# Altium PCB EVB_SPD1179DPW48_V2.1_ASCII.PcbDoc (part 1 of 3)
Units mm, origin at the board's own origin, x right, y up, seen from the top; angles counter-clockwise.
Board outline 135 x 90 mm, 4 copper layers (Top Layer, GND, L3, Bottom Layer), stack 0.603 mm thick; 322 components, 156 nets, 727 pads, 939 vias.
Unrouted connection lines stored in the file: 172.
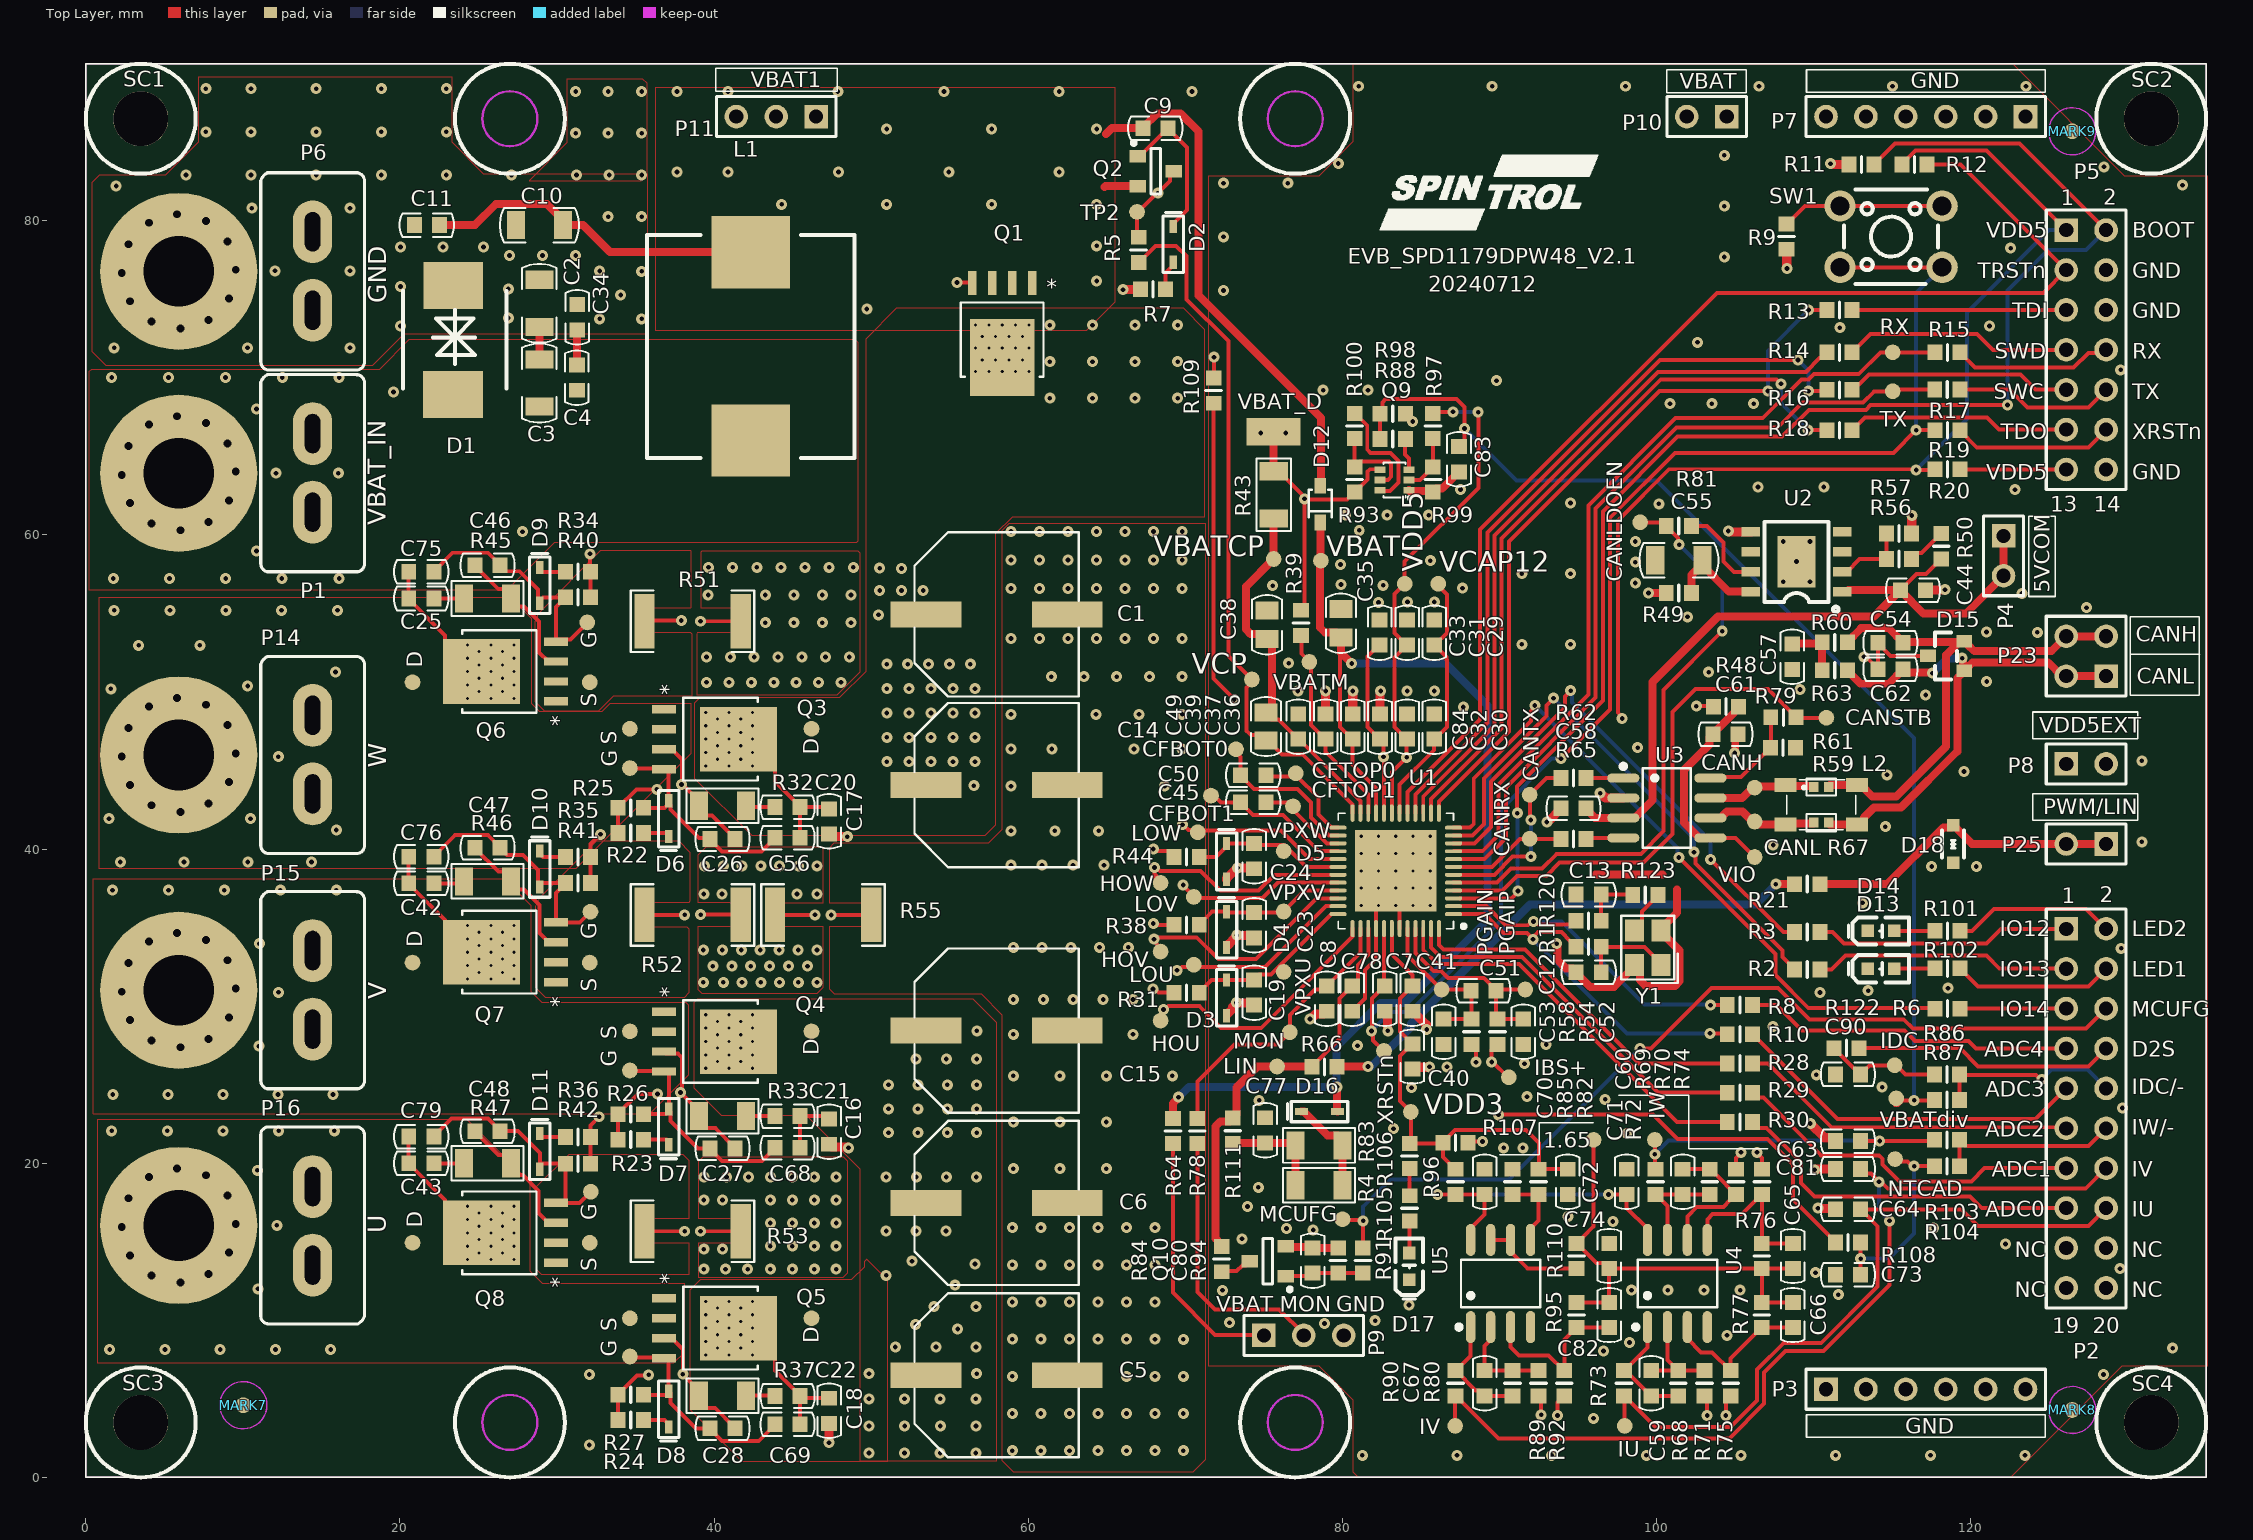
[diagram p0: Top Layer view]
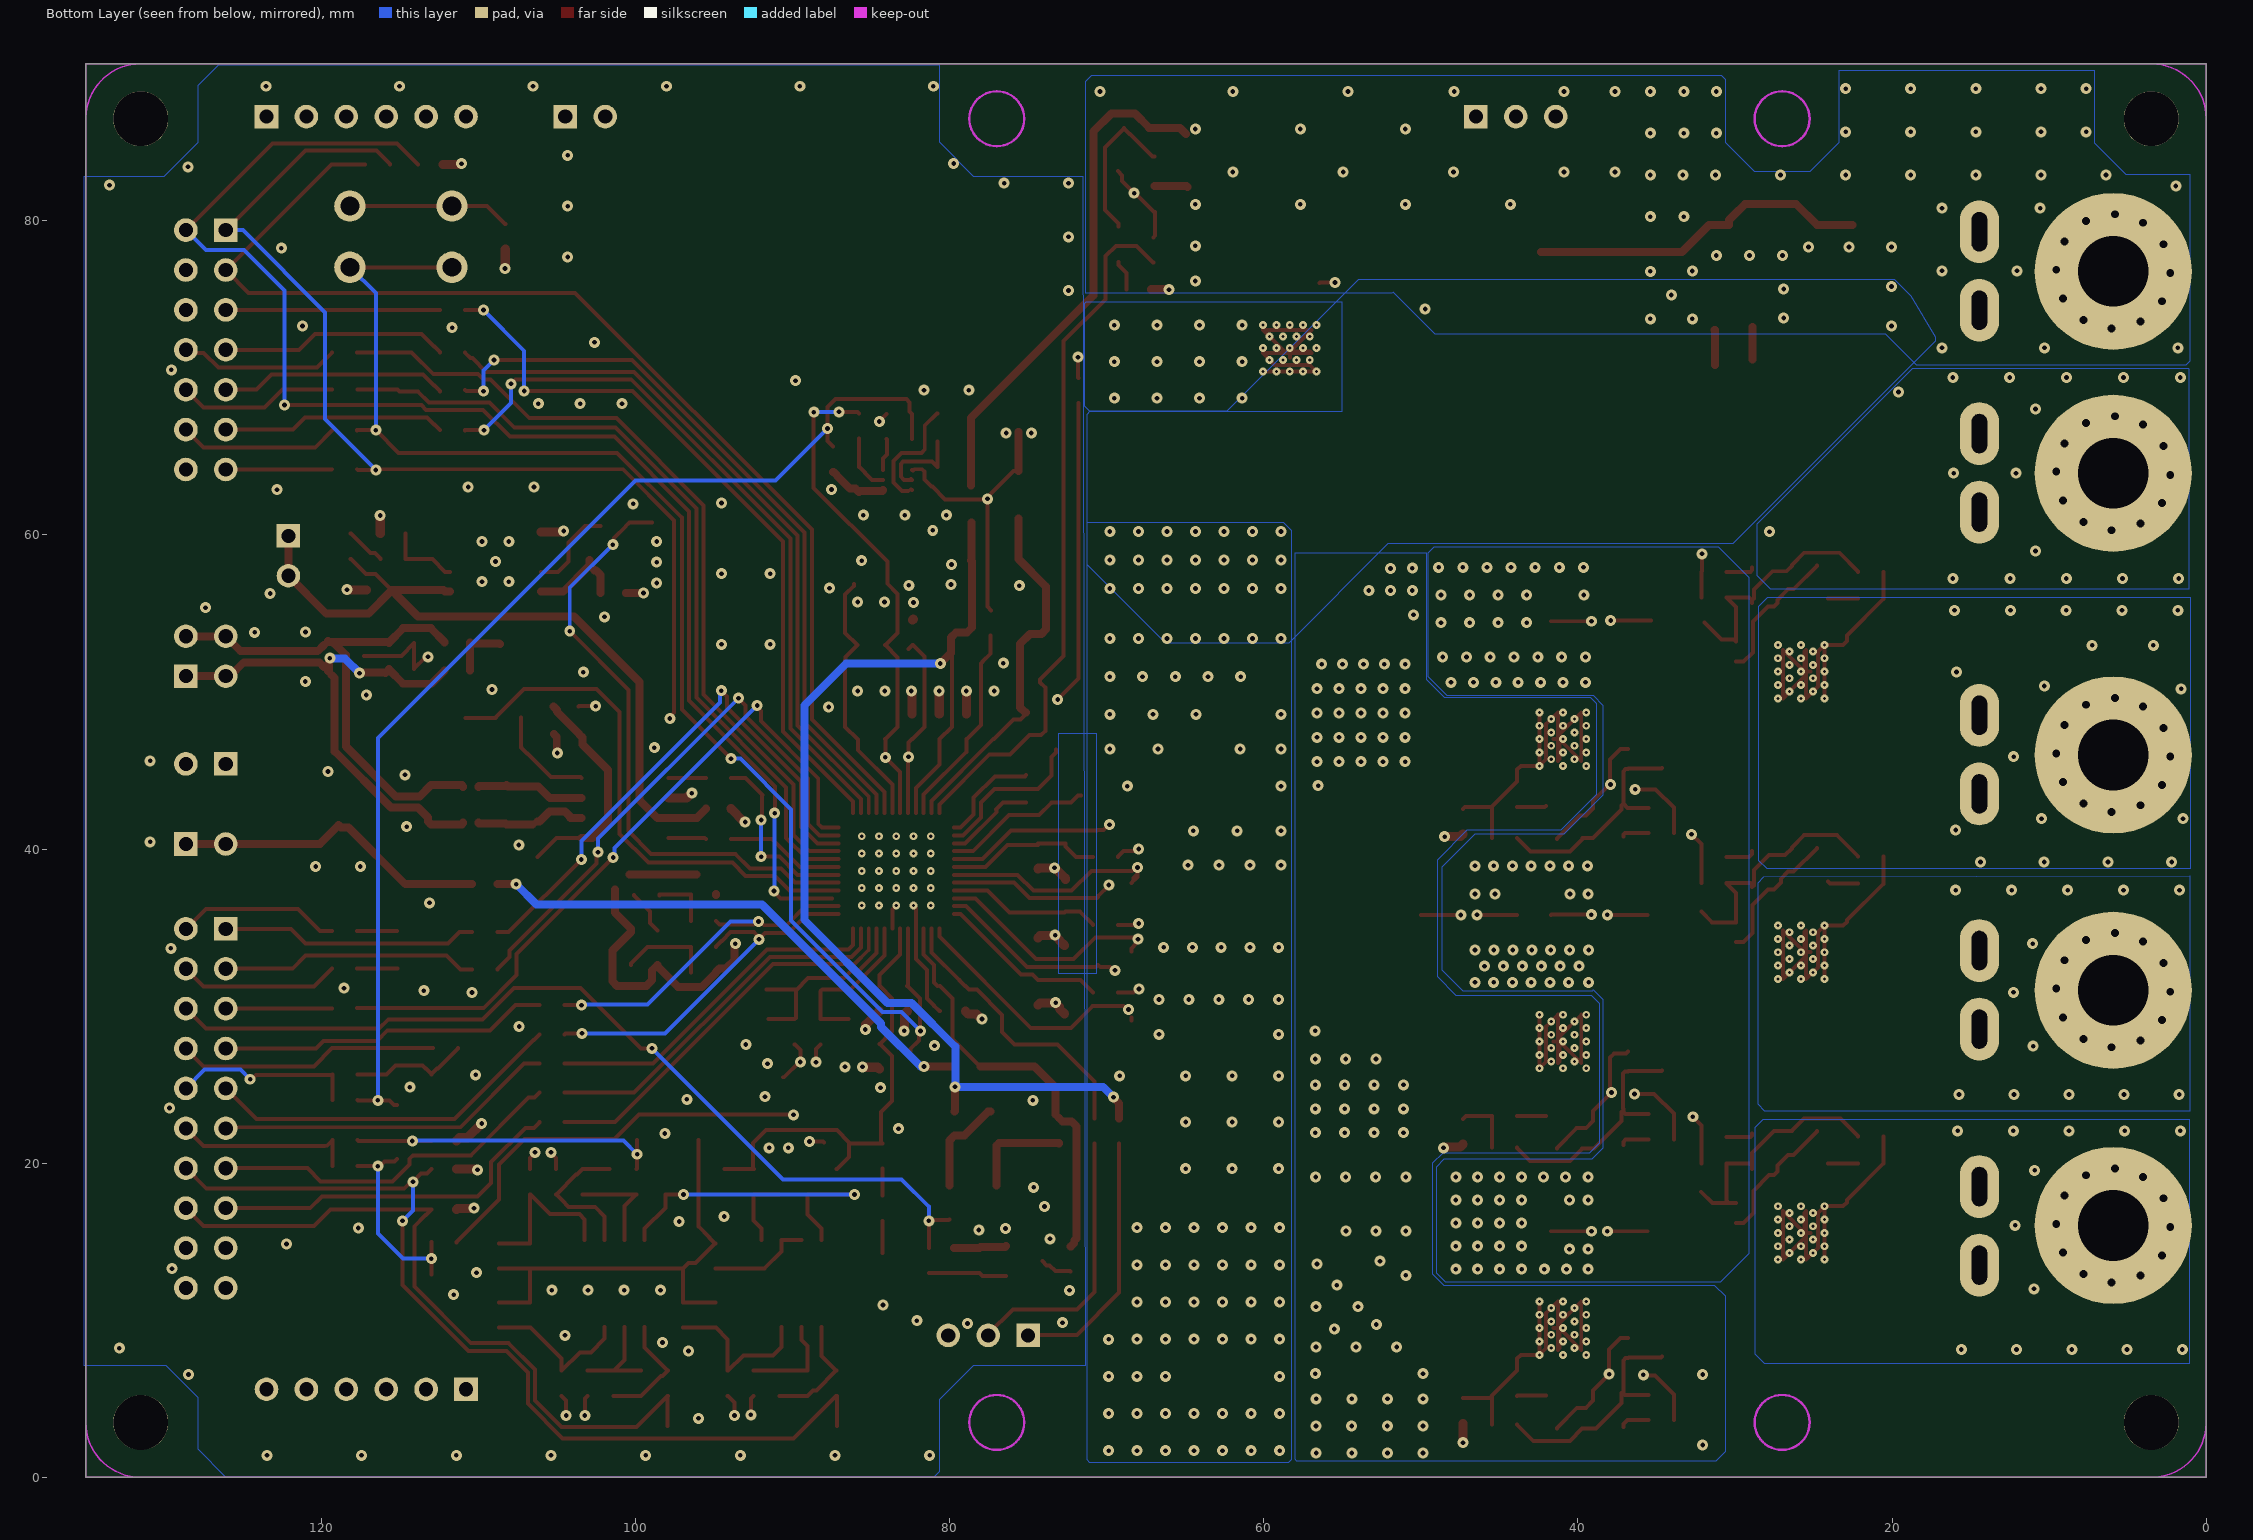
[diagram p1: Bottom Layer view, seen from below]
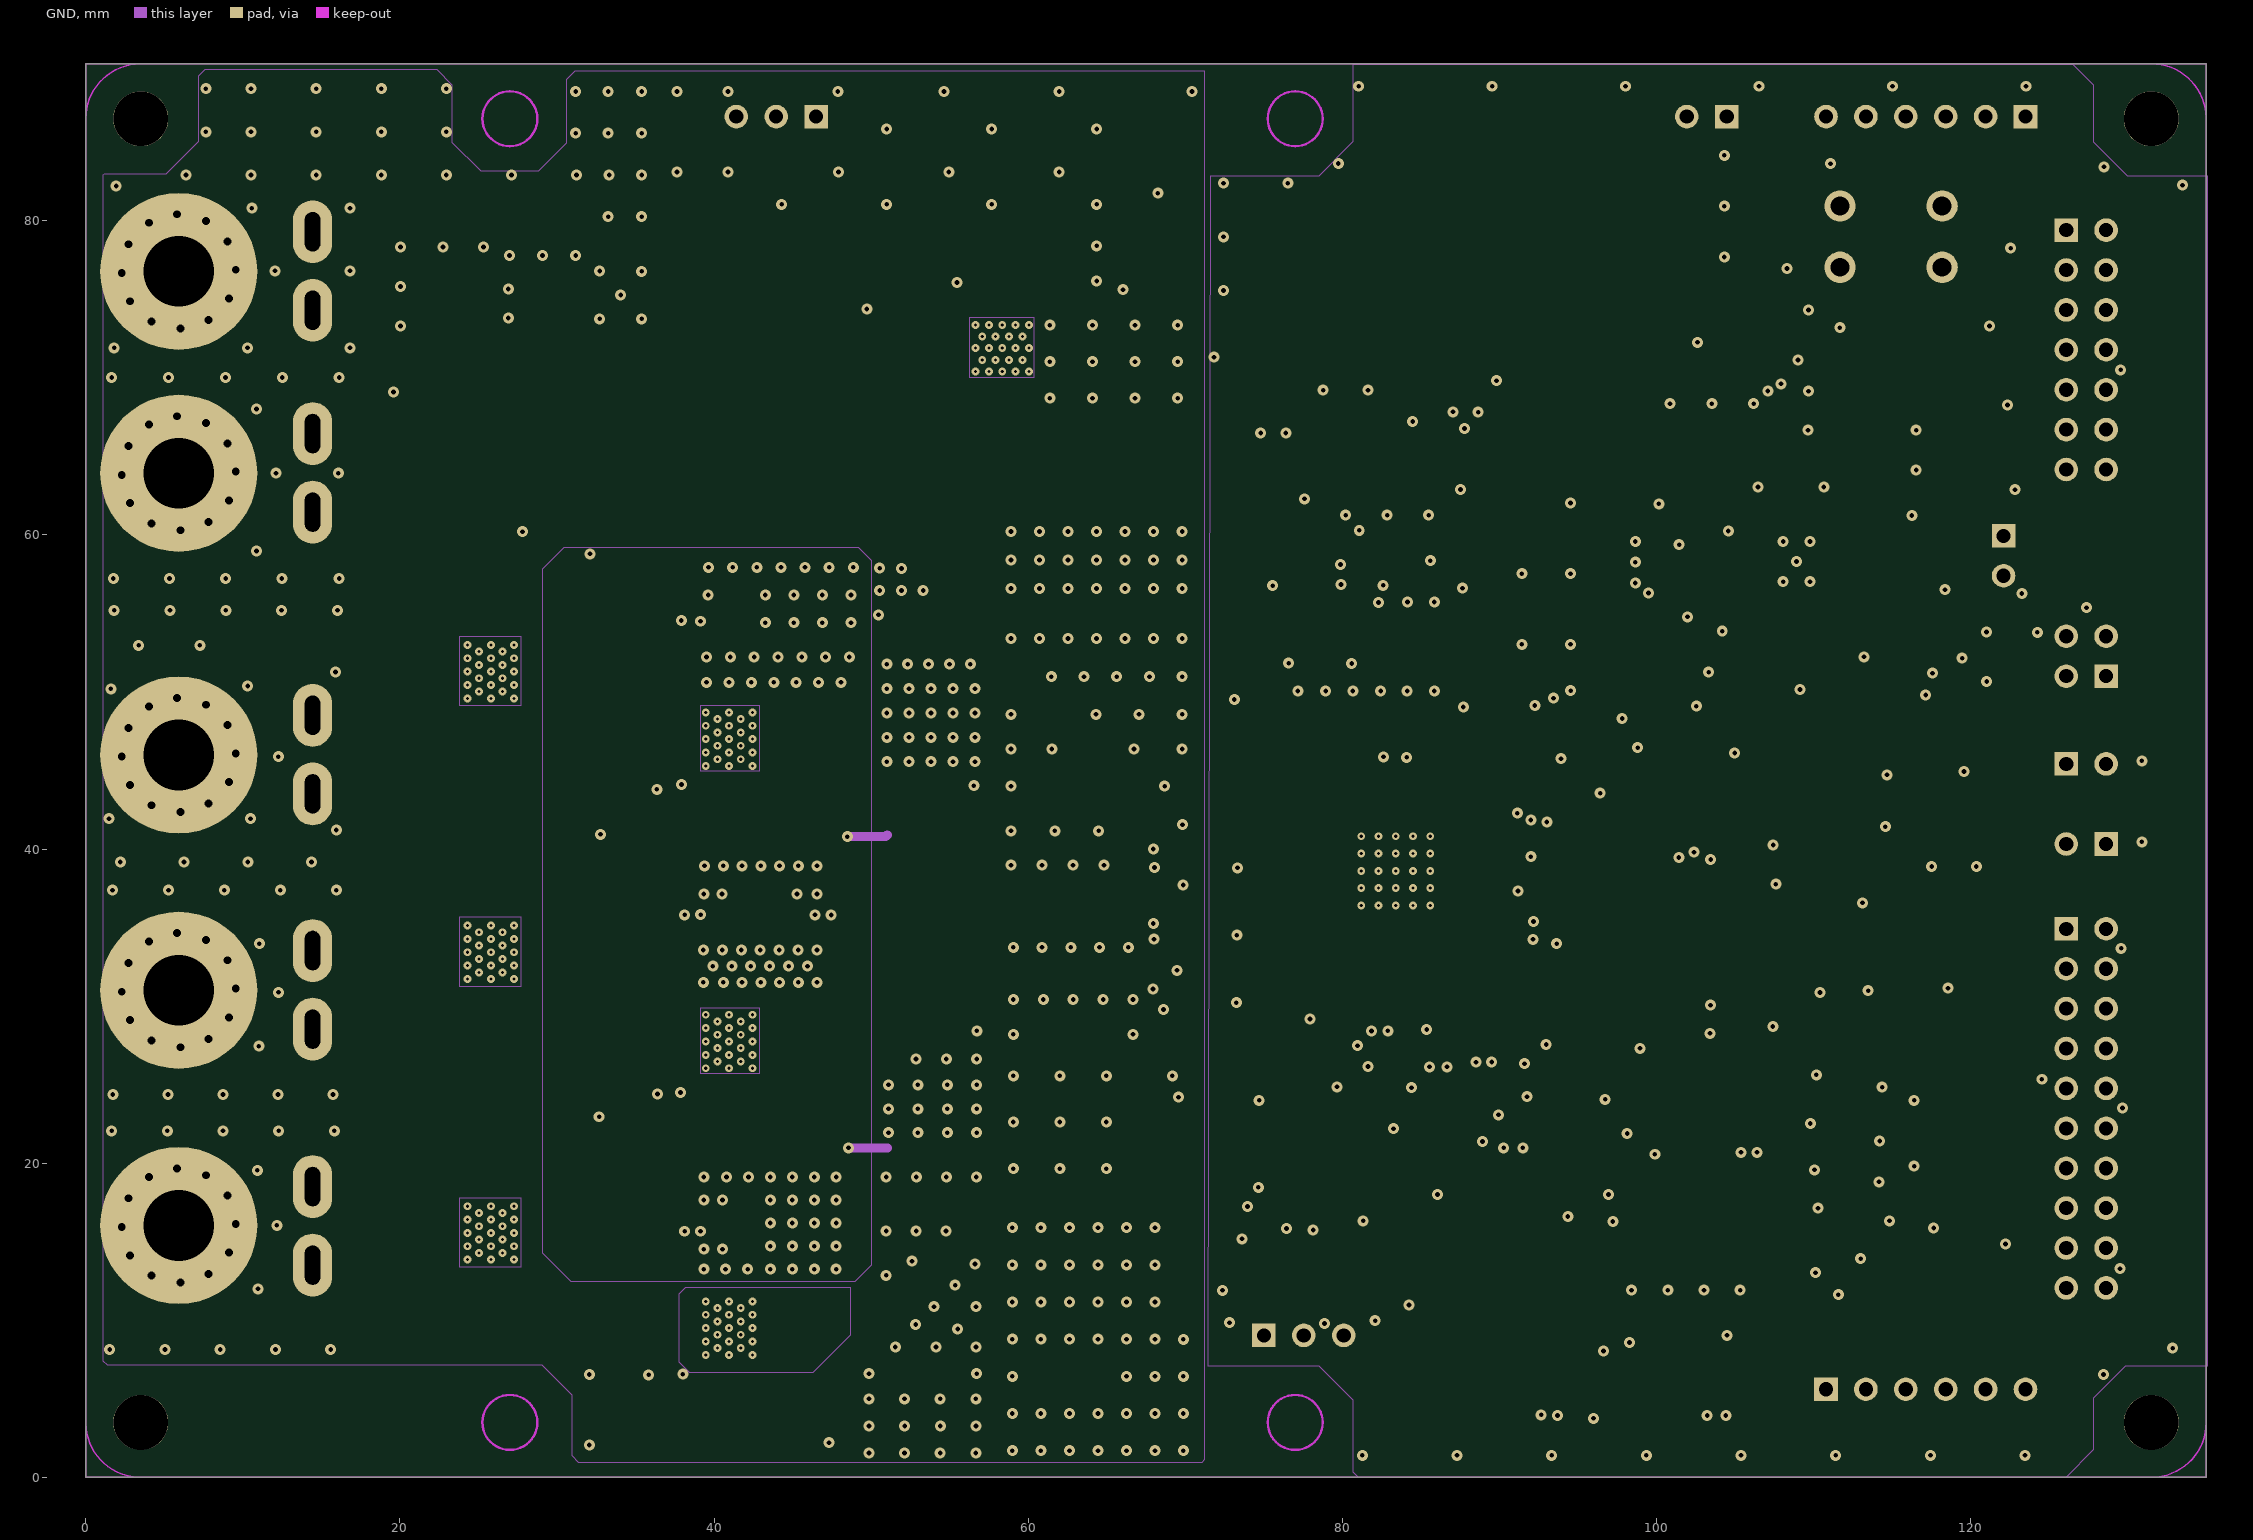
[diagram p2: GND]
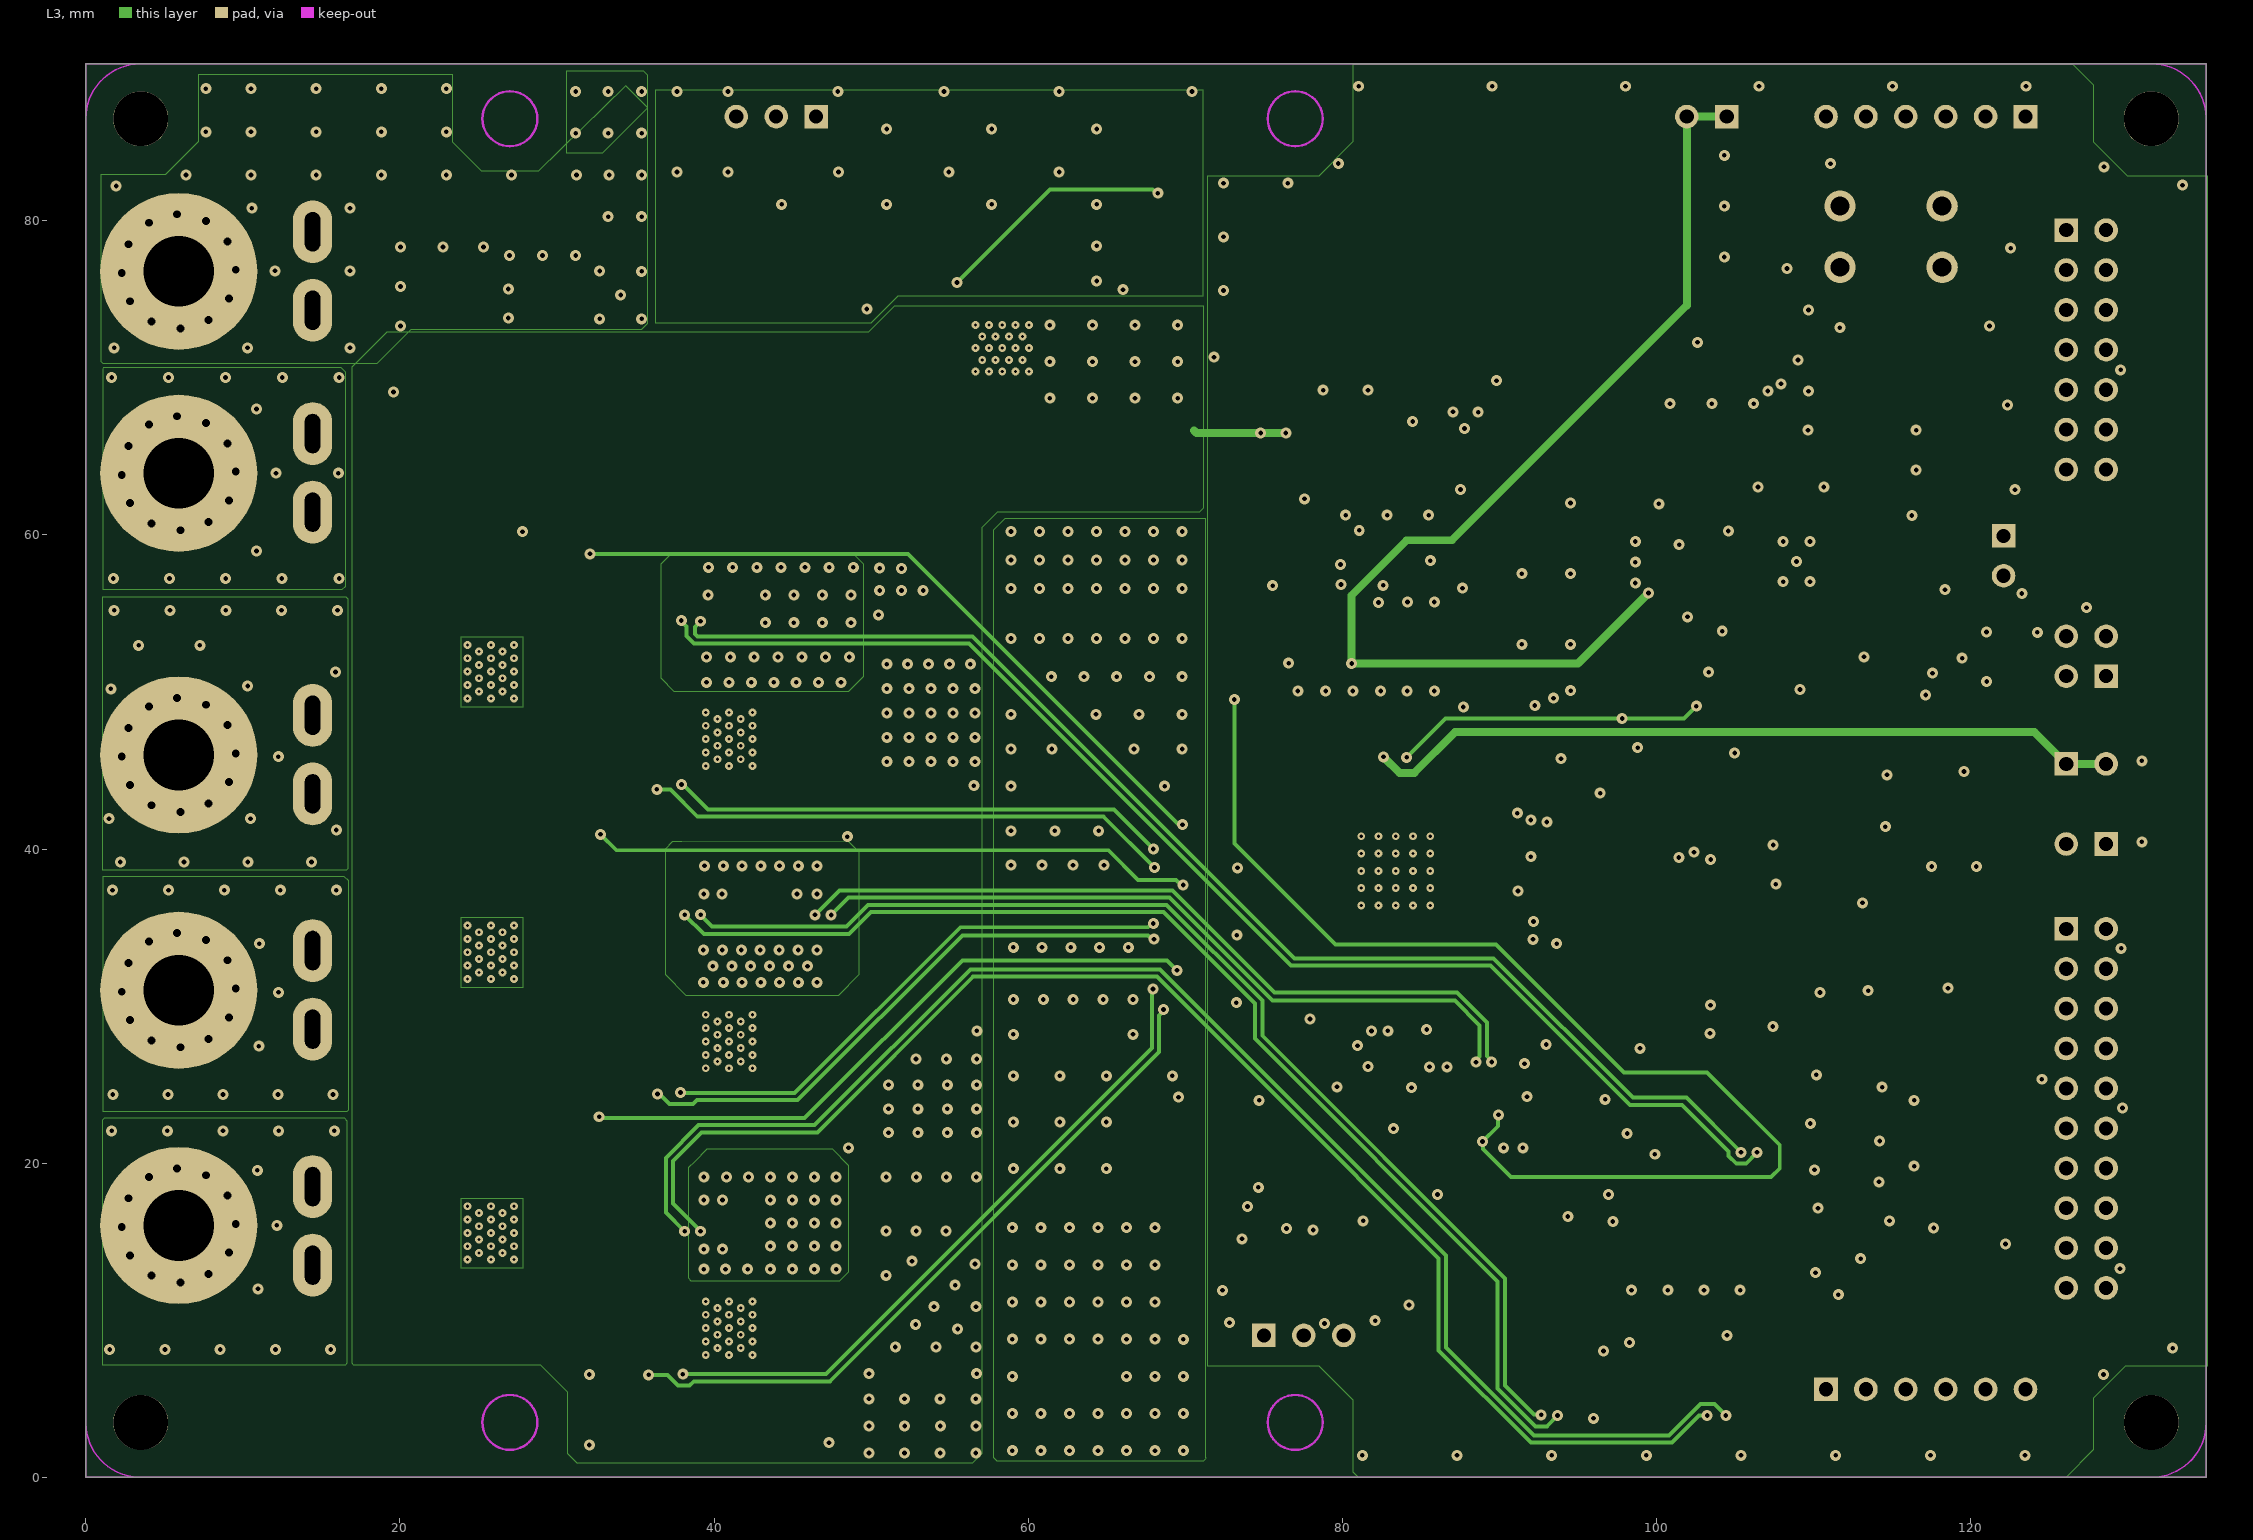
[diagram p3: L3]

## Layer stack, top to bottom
Top Solder: solder mask 0.0102, Solder Resist, Dk 3.5
Top Layer: signal copper 0.0356
Dielectric 2: prepreg 0.0711, PP-006, Dk 4.1
GND: signal copper 0.035
Dielectric 1: dielectric 0.32, FR-4, Dk 4.8
L3: signal copper 0.035
Dielectric 3: prepreg 0.0711, PP-006, Dk 4.1
Bottom Layer: signal copper 0.0356
Bottom Solder: solder mask 0.0102, Solder Resist, Dk 3.5

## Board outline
0,0 135,0 135,90 0,90

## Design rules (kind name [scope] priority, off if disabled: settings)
AssemblyTestPointUsage [All] p0: scope1count=1 scope1_0_kind=Board scope1_0_value=Board scope2count=1 scope2_0_kind=Board scope2_0_value=Board commentlength=0
AssemblyTestpoint [All] p0: scope1count=1 scope1_0_kind=Board scope1_0_value=Board scope2count=1 scope2_0_kind=Board scope2_0_value=Board commentlength=0
Clearance Clearance_LC [All] p0 off: scope1count=1 scope1_0_kind=Board scope1_0_value=Board scope2count=1 scope2_0_kind=Board scope2_0_value=Board commentlength=59 gap=0.3 // Protel DXP Scope 1 Expression Was: InNamedPolygon('LC')
Clearance Clearance_keepout [All] p0 off: scope1count=1 scope1_0_kind=Board scope1_0_value=Board scope2count=1 scope2_0_kind=Board scope2_0_value=Board commentlength=48 gap=1 // Protel DXP Scope 1 Expression Was: IsKeepOut
Clearance [All] p0: scope1count=1 scope1_0_kind=Board scope1_0_value=Board scope2count=1 scope2_0_kind=Board scope2_0_value=Board commentlength=0 gap=0.5
Clearance Clearance_LC [InNamedPolygon('LC')] p1: gap=0.3 ignorepadtopadclearanceinfootprint=FALSE except(0: Arc-Hole Track-Hole SMDPad-Hole THPad-Hole Via-Hole Fill-Hole Poly-Hole Region-Hole Text-Hole; 0.178: Arc-SMDPad Track-SMDPad SMDPad-SMDPad; 0.203: Arc-Arc Arc-Track Track-Track; 0.254: Arc-THPad Arc-Via Arc-Text Track-THPad Track-Via Track-Text SMDPad-THPad SMDPad-Via SMDPad-Text THPad-THPad THPad-Via THPad-Text Via-Via Via-Text Fill-Text Poly-Text Region-Text Text-Text)
Clearance Clearance_keepout [IsKeepOut] p2: gap=1 ignorepadtopadclearanceinfootprint=FALSE except(0: Arc-Hole Track-Hole SMDPad-Hole THPad-Hole Via-Hole Fill-Hole Poly-Hole Region-Hole Text-Hole; 0.178: Arc-SMDPad Track-SMDPad SMDPad-SMDPad; 0.203: Arc-Arc Arc-Track Track-Track; 0.254: Arc-THPad Arc-Via Arc-Text Track-THPad Track-Via Track-Text SMDPad-THPad SMDPad-Via SMDPad-Text THPad-THPad THPad-Via THPad-Text Via-Via Via-Text Fill-Text Poly-Text Region-Text Text-Text)
Clearance [All] p3: gap=0.5 ignorepadtopadclearanceinfootprint=FALSE except(0: Arc-Hole Track-Hole SMDPad-Hole THPad-Hole Via-Hole Fill-Hole Poly-Hole Region-Hole Text-Hole; 0.178: Arc-SMDPad Track-SMDPad SMDPad-SMDPad; 0.203: Arc-Arc Arc-Track Track-Track; 0.254: Arc-THPad Arc-Via Arc-Text Track-THPad Track-Via Track-Text SMDPad-THPad SMDPad-Via SMDPad-Text THPad-THPad THPad-Via THPad-Text Via-Via Via-Text Fill-Text Poly-Text Region-Text Text-Text)
ComponentClearance [All] p0: scope1count=1 scope1_0_kind=Board scope1_0_value=Board scope2count=1 scope2_0_kind=Board scope2_0_value=Board commentlength=0 gap=0.05 collisioncheckmode=3
ComponentClearance [All] p1: gap=0.05 collisioncheckmode=3 verticalgap=0.05 showdistances=FALSE
DiffPairsRouting [All] p0: scope1count=1 scope1_0_kind=Board scope1_0_value=Board scope2count=1 scope2_0_kind=Board scope2_0_value=Board commentlength=0
FabricationTestPointUsage [All] p0: scope1count=1 scope1_0_kind=Board scope1_0_value=Board scope2count=1 scope2_0_kind=Board scope2_0_value=Board commentlength=0 valid=0 allowmultiple=FALSE
FabricationTestpoint [All] p0: scope1count=1 scope1_0_kind=Board scope1_0_value=Board scope2count=1 scope2_0_kind=Board scope2_0_value=Board commentlength=0 side=3 testpointundercomponent=TRUE minsize=1.016 maxsize=2.54 preferedsize=1.524 minholesize=0 maxholesize=1.016 preferedholesize=0.813 testpointgrid=0.025
FanoutControl Fanout_BGA [All] p0 off: scope1count=1 scope1_0_kind=Board scope1_0_value=Board scope2count=1 scope2_0_kind=Board scope2_0_value=Board commentlength=69 // Protel DXP Scope 1 Expression Was: IsBGA   Fanout_BGA (Default Rule)
FanoutControl Fanout_LCC [All] p0 off: scope1count=1 scope1_0_kind=Board scope1_0_value=Board scope2count=1 scope2_0_kind=Board scope2_0_value=Board commentlength=69 // Protel DXP Scope 1 Expression Was: IsLCC   Fanout_LCC (Default Rule)
FanoutControl Fanout_SOIC [All] p0 off: scope1count=1 scope1_0_kind=Board scope1_0_value=Board scope2count=1 scope2_0_kind=Board scope2_0_value=Board commentlength=71 // Protel DXP Scope 1 Expression Was: IsSOIC   Fanout_SOIC (Default Rule)
FanoutControl Fanout_Small [All] p0 off: scope1count=1 scope1_0_kind=Board scope1_0_value=Board scope2count=1 scope2_0_kind=Board scope2_0_value=Board commentlength=84 // Protel DXP Scope 1 Expression Was: (CompPinCount < 5)   Fanout_Small (Default Rule)
FanoutControl Fanout_Default [All] p0: scope1count=1 scope1_0_kind=Board scope1_0_value=Board scope2count=1 scope2_0_kind=Board scope2_0_value=Board commentlength=30 // Fanout_Default (Default Rule)
Height [All] p0: scope1count=1 scope1_0_kind=Board scope1_0_value=Board scope2count=1 scope2_0_kind=Board scope2_0_value=Board commentlength=0
HoleSize [All] p0: scope1count=1 scope1_0_kind=Board scope1_0_value=Board scope2count=1 scope2_0_kind=Board scope2_0_value=Board commentlength=0 absolutevalues=TRUE maxlimit=10 minlimit=0.025 maxpercent=80.000 minpercent=20.000
HoleSize [All] p1: absolutevalues=TRUE maxlimit=10 minlimit=0.025 maxpercent=80.000 minpercent=20.000
HoleToHoleClearance [All] p0: scope1count=1 scope1_0_kind=Board scope1_0_value=Board scope2count=1 scope2_0_kind=Board scope2_0_value=Board commentlength=0
HoleToHoleClearance [All] p1: gap=0.1 allowstackedmicrovias=TRUE
LayerPairs [All] p0: scope1count=1 scope1_0_kind=Board scope1_0_value=Board scope2count=1 scope2_0_kind=Board scope2_0_value=Board commentlength=0 enforce=TRUE
MinimumSolderMaskSliver [All] p0: scope1count=1 scope1_0_kind=Board scope1_0_value=Board scope2count=1 scope2_0_kind=Board scope2_0_value=Board commentlength=0
MinimumSolderMaskSliver [All] p1: minsoldermaskwidth=0.02
NetAntennae [All] p0: scope1count=1 scope1_0_kind=Board scope1_0_value=Board scope2count=1 scope2_0_kind=Board scope2_0_value=Board commentlength=0
PasteMaskExpansion [All] p0: scope1count=1 scope1_0_kind=Board scope1_0_value=Board scope2count=1 scope2_0_kind=Board scope2_0_value=Board commentlength=0 expansion=0
PlaneClearance [All] p0: scope1count=1 scope1_0_kind=Board scope1_0_value=Board scope2count=1 scope2_0_kind=Board scope2_0_value=Board commentlength=0 clearance=0.508
PlaneConnect [All] p0: scope1count=1 scope1_0_kind=Board scope1_0_value=Board scope2count=1 scope2_0_kind=Board scope2_0_value=Board commentlength=0 planeconnectstyle=Relief reliefexpansion=0.508 reliefentries=4 reliefconductorwidth=0.254 reliefairgap=0.254
PolygonConnect PolygonConnect_1 [All] p0: scope1count=1 scope1_0_kind=Footprint scope1_0_value=TP-1.0 scope2count=1 scope2_0_kind=Board scope2_0_value=Board commentlength=0 connectstyle=Direct reliefconductorwidth=0.254 reliefentries=4 polygonreliefangle="90 Angle"
PolygonConnect PolygonConnect_direct [All] p0: scope1count=1 scope1_0_kind=ComponentClass scope1_0_value=direct scope2count=1 scope2_0_kind=Board scope2_0_value=Board commentlength=0 connectstyle=Direct reliefconductorwidth=0.254 reliefentries=4 polygonreliefangle="90 Angle"
PolygonConnect [All] p0: scope1count=1 scope1_0_kind=Board scope1_0_value=Board scope2count=1 scope2_0_kind=Board scope2_0_value=Board commentlength=0 connectstyle=Direct reliefconductorwidth=0.254 reliefentries=4 polygonreliefangle="90 Angle"
PolygonConnect PolygonConnect_1 [HasFootprint('TP-1.0')] p1: connectstyle=Direct reliefconductorwidth=0.254 reliefentries=4 polygonreliefangle="90 Angle" airgapwidth=0.254
PolygonConnect PolygonConnect_direct [InComponentClass('direct')] p2: connectstyle=Direct reliefconductorwidth=0.254 reliefentries=4 polygonreliefangle="90 Angle" airgapwidth=0.254
PolygonConnect [All] p3: thpad.connectstyle=Direct thpad.reliefconductorwidth=0.254 thpad.reliefentries=4 thpad.polygonreliefangle="90 Angle" thpad.airgapwidth=0.254 smdpad.connectstyle=Relief smdpad.reliefconductorwidth=0.254 smdpad.reliefentries=4 smdpad.polygonreliefangle="90 Angle" smdpad.airgapwidth=0.254 via.connectstyle=Direct via.reliefconductorwidth=0.254 via.reliefentries=4 via.polygonreliefangle="90 Angle" via.airgapwidth=0.254
RoutingCorners [All] p0: scope1count=1 scope1_0_kind=Board scope1_0_value=Board scope2count=1 scope2_0_kind=Board scope2_0_value=Board commentlength=0 cornerstyle=45-Degree minsetback=2.54 maxsetback=2.54
RoutingLayers [All] p0: scope1count=1 scope1_0_kind=Board scope1_0_value=Board scope2count=1 scope2_0_kind=Board scope2_0_value=Board commentlength=0 top layer=Automatic mid layer 1=Automatic mid layer 2=Automatic bottom layer=Automatic
RoutingPriority [All] p0: scope1count=1 scope1_0_kind=Board scope1_0_value=Board scope2count=1 scope2_0_kind=Board scope2_0_value=Board commentlength=0
RoutingTopology [All] p0: scope1count=1 scope1_0_kind=Board scope1_0_value=Board scope2count=1 scope2_0_kind=Board scope2_0_value=Board commentlength=0 topology=Shortest
RoutingVias [All] p0: scope1count=1 scope1_0_kind=Board scope1_0_value=Board scope2count=1 scope2_0_kind=Board scope2_0_value=Board commentlength=0 holewidth=0.711 width=1.27 viastyle="Through Hole" minholewidth=0.711 minwidth=1.27 maxholewidth=0.711 maxwidth=1.27
RoutingVias [All] p1: holewidth=0.711 width=1.27 viastyle="Through Hole" minholewidth=0.711 minwidth=1.27 maxholewidth=0.711 maxwidth=1.27
ShortCircuit [All] p0: scope1count=1 scope1_0_kind=Board scope1_0_value=Board scope2count=1 scope2_0_kind=Board scope2_0_value=Board commentlength=0 allowed=FALSE
SilkToBoardRegionClearance [All] p0: scope1count=1 scope1_0_kind=Board scope1_0_value=Board scope2count=1 scope2_0_kind=Board scope2_0_value=Board commentlength=0
SilkToSilkClearance [All] p0: scope1count=1 scope1_0_kind=Board scope1_0_value=Board scope2count=1 scope2_0_kind=Board scope2_0_value=Board commentlength=0
SilkToSilkClearance [All] p1: silktosilkclearance=0.01
SilkToSolderMaskClearance [All] p0 off: scope1count=1 scope1_0_kind=Board scope1_0_value=Board scope2count=1 scope2_0_kind=Board scope2_0_value=Board commentlength=44 // Protel DXP Scope 1 Expression Was: IsPad
SilkToSolderMaskClearance [IsPad] p1: minsilkscreentomaskgap=0.01 clearancetoexposedcopper=TRUE
SolderMaskExpansion [All] p0: scope1count=1 scope1_0_kind=Board scope1_0_value=Board scope2count=1 scope2_0_kind=Board scope2_0_value=Board commentlength=0 expansion=0.102
SolderMaskExpansion [All] p1: expansion=0.102 istentingtop=FALSE
UnRoutedNet [All] p0: scope1count=1 scope1_0_kind=Board scope1_0_value=Board scope2count=1 scope2_0_kind=Board scope2_0_value=Board commentlength=0
UnpouredPolygon [All] p0: scope1count=1 scope1_0_kind=Board scope1_0_value=Board scope2count=1 scope2_0_kind=Board scope2_0_value=Board commentlength=0
Width [All] p0: scope1count=1 scope1_0_kind=Board scope1_0_value=Board scope2count=1 scope2_0_kind=Board scope2_0_value=Board commentlength=0 maxlimit=2.54 minlimit=0.203 preferedwidth=0.254
Width [All] p1: maxlimit=2.54 minlimit=0.203 preferedwidth=0.254
24 further rules are at their usual default settings.

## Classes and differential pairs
component class SPD1179_Demo_Board: 1.65 C1 C2 C3 C4 C5 C6 C7 C8 C9 C10 C11 C12 C13 C14 C15 C16 C17 C18 C19 C20 C21 C22 C23 C24 C25 C26 C27 C28 C29 C30 C31 C32 C33 C34 C35 C36 C37 C38 C39 C40 C41 C42 C43 C44 C45 C46 C47 C48 C49 C50 C51 C52 C53 C54 C55 C56 C57 C58 C59 C60 C61 C62 C63 C64 C65 C66 C67 C68 C69 C70 C71 C72 C73 C74 C75 C76 C77 C78 C79 C80 C81 C82 C83 C84 C90 CANH CANL CANLDOEN CANRX CANSTB CANTX CFBOT0 CFBOT1 CFTOP0 CFTOP1 D D1 D2 D3 D4 D5 D6 D7 D8 D9 D10 D11 D12 D13 D14 D15 D16 D17 D18 G HOU HOV HOW IBS+ IDC IU IV IW L1 L2 LIN LOU LOV LOW MCUFG MON NTCAD P1 P2 P3 P4 P5 P6 P7 P8 P9 P10 P14 P15 P16 P23 P25 PGAIN PGAIP Q1 Q2 Q3 Q4 Q5 Q6 Q7 Q8 Q9 Q10 R1 R2 R3 R4 R5 R6 R7 R8 R9 R10 R11 R12 R13 R14 R15 R16 R17 R18 R19 R20 R21 R22 R23 R24 R25 R26 R27 R28 R29 R30 R31 R32 R33 R34 R35 R36 R37 R38 R39 R40 R41 R42 R43 R44 R45 R46 R47 R48 R49 R50 R51 R52 R53 R54 R55 R56 R57 R58 R59 R60 R61 R62 R63 R64 R65 R66 R67 R68 R69 R70 R71 R72 R73 R74 R75 R76 R77 R78 R79 R80 R81 R82 R83 R84 R85 R86 R87 R88 R89 R90 R91 R92 R93 R94 R95 R96 R97 R98 R99 R100 R101 R102 R103 R104 R105 R106 R107 R108 R109 R110 R111 R120 R122 R123 RX S SW1 TP2 TX U1 U2 U3 U4 U5 VBAT VBAT_D VBATCP VBATDDIV VBATM VCAP12 VCP VDD3 VDD5 VIO VPXU VPXV VPXW Y1

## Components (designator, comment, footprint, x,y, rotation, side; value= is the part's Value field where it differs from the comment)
1.65 "TEST-Point" TP-1.0 95.996,21.488 r180 top (schematic designator TP35)
C1 "EEHZK1E471P" CAP-SMD_BD10.0-L10.3-W10.3-FD 57.988,54.947 r0 top
C2 "CAP" C1206 28.88,74.752 r270 top
C3 "CAP" C1206 28.88,69.672 r270 top
C4 "CAP" C0603 31.267,70.015 r270 top
C5 "EEHZK1E471P" CAP-SMD_BD10.0-L10.3-W10.3-FD 57.988,6.502 r0 top
C6 "EEHZK1E471P" CAP-SMD_BD10.0-L10.3-W10.3-FD 57.988,17.475 r0 top
C7 "CAP" C0603 82.703,30.48 r90 top
C8 "CAP" C0603 79.003,30.48 r90 top
C9 "CAP" C0603 68.097,85.903 r180 top
C10 "CAP" C1206 28.88,79.731 r180 top
C11 "CAP" C0603 21.717,79.731 r0 top
C12 "CAP" C0603 95.682,32.156 r0 top
C13 "CAP" C0603 95.682,37.109 r0 top
C14 "EEHZK1E471P" CAP-SMD_BD10.0-L10.3-W10.3-FD 57.988,44.076 r0 top
C15 "EEHZK1E471P" CAP-SMD_BD10.0-L10.3-W10.3-FD 57.988,28.448 r0 top
C16 "CAP" C0603 47.32,22.012 r90 top
C17 "CAP" C0603 47.32,41.764 r90 top
C18 "CAP" C0603 47.32,4.242 r90 top
C19 "NC" C0603 74.381,30.864 r90 top
C20 "CAP" C0603 44.679,42.679 r0 top
C21 "CAP" C0603 44.679,23.003 r0 top
C22 "CAP" C0603 44.679,5.182 r0 top
C23 "NC" C0603 74.381,35.154 r90 top
C24 "NC" C0603 74.381,39.551 r90 top
C25 "CAP" C0603 21.361,55.956 r180 top
C26 "CAP" C0603 40.538,40.647 r180 top
C27 "CAP" C0603 40.538,20.946 r180 top
C28 "CAP" C0603 40.538,3.124 r180 top
C29 "CAP" C0603 85.852,53.784 r270 top
C30 "CAP" C0603 85.852,47.803 r270 top
C31 "CAP" C0603 84.122,53.784 r270 top
C32 "CAP" C0603 84.122,47.803 r270 top
C33 "CAP" C0603 82.372,53.785 r270 top
C34 "CAP" C0603 31.293,73.863 r270 top
C35 "CAP" C0805 79.908,54.381 r270 top
C36 "CAP" C0603 80.661,47.803 r270 top
C37 "CAP" C0603 78.93,47.803 r270 top
C38 "CAP" C0805 75.209,54.28 r270 top
C39 "CAP" C0603 77.2,47.803 r270 top
C40 "CAP" C0603 84.464,26.797 r90 top
C41 "CAP" C0603 84.464,30.48 r90 top
C42 "CAP" C0603 21.361,37.819 r180 top
C43 "CAP" C0603 21.361,19.998 r180 top
C44 "CAP" C0603 116.332,56.49 r180 top
C45 "CAP" C0603 74.33,42.977 r180 top
C46 "CAP" C0603 25.578,58.064 r0 top
C47 "CAP" C0603 25.578,40.08 r0 top
C48 "CAP" C0603 25.578,22.047 r0 top
C49 "CAP" C0805 75.143,47.803 r90 top
C50 "CAP" C0603 74.33,44.704 r0 top
C51 "CAP" C0603 88.986,30.988 r0 top
C52 "CAP" C0603 91.526,28.372 r90 top
C53 "CAP" C0603 86.446,28.372 r90 top
C54 "CAP" C0603 114.897,53.137 r0 top
C55 "CAP" C1206 101.422,58.395 r0 top
C56 "NC" C0603 44.679,40.723 r180 top
C57 "CAP" C0603 108.636,52.248 r90 top
C58 "CAP" C0603 94.717,42.596 r0 top
C59 "CAP" C0603 99.662,5.994 r90 top
C60 "CAP" C0603 101.662,18.821 r90 top
C61 "CAP" C0603 104.394,47.32 r180 top
C62 "CAP" C0603 114.897,51.46 r0 top
C63 "CAP" C0603 112.192,21.412 r0 top
C64 "CAP" C0603 112.192,17.069 r0 top
C65 "CAP" C0603 108.687,14.097 r90 top
C66 "CAP" C0603 108.687,10.338 r270 top
C67 "CAP" C0603 89.057,5.994 r90 top
C68 "NC" C0603 44.679,20.996 r180 top
C69 "NC" C0603 44.679,3.378 r180 top
C70 "CAP" C0603 89.057,18.821 r270 top
C71 "CAP" C0603 98.106,18.821 r270 top
C72 "CAP" C0603 94.345,18.821 r90 top
C73 "CAP" C0603 112.192,12.903 r0 top
C74 "CAP" C0603 96.987,14.097 r270 top
C75 "NC" C0603 21.361,57.658 r0 top
C76 "NC" C0603 21.361,39.521 r0 top
C77 "" C0603 75.082,22.098 r270 top
C78 "CAP" C0603 80.629,30.48 r90 top
C79 "NC" C0603 21.361,21.7 r0 top
C80 "CAP" C0603 78.105,13.805 r270 top
C81 "CAP" C0603 112.192,19.634 r0 top
C82 "CAP" C0603 96.987,10.338 r270 top
C83 "CAP" C0603 87.427,64.823 r90 top
C84 "CAP" C0603 82.398,47.803 r270 top
C90 "CAP" C0603 112.192,25.654 r0 top
CANH "TEST-Point" TP-1.0 106.248,43.917 r90 top (schematic designator TP29)
CANL "TEST-Point" TP-1.0 106.248,41.758 r90 top (schematic designator TP31)
CANLDOEN "TEST-Point" TP-1.0 98.958,60.808 r270 top (schematic designator TP30)
CANRX "TEST-Point" TP-1.0 91.923,40.665 r90 top (schematic designator TP63)
CANSTB "TEST-Point" TP-1.0 110.82,48.362 r90 top (schematic designator TP48)
CANTX "TEST-Point" TP-1.0 91.923,43.459 r90 top (schematic designator TP62)
CFBOT0 "TEST-Point" TP-1.0 73.228,46.355 r90 top (schematic designator TP41)
CFBOT1 "TEST-Point" TP-1.0 71.637,43.409 r270 top (schematic designator TP39)
CFTOP0 "TEST-Point" TP-1.0 77.038,44.831 r90 top (schematic designator TP43)
CFTOP1 "TEST-Point" TP-1.0 76.86,42.723 r90 top (schematic designator TP42)
D "TEST-Point" TP-1.0 20.803,50.622 r90 top (schematic designator TP18)
D "TEST-Point" TP-1.0 20.803,14.935 r90 top (schematic designator TP17)
D "TEST-Point" TP-1.0 20.803,32.779 r180 top (schematic designator TP16)
D "TEST-Point" TP-1.0 46.203,28.397 r0 top (schematic designator TP6)
D "TEST-Point" TP-1.0 46.203,10.135 r0 top (schematic designator TP5)
D "TEST-Point" TP-1.0 46.203,47.66 r0 top (schematic designator TP4)
D1 "" SMC/DO-214AB/Bidirect 23.495,72.593 r90 top
D2 "DIODE" SODFL2513X100/SOD323F/SC-90 69.24,78.508 r270 top
D3 "NC" SODFL2513X100/SOD323F/SC-90 72.628,30.531 r270 top
D4 "NC" SODFL2513X100/SOD323F/SC-90 72.628,34.874 r270 top
D5 "NC" SODFL2513X100/SOD323F/SC-90 72.628,39.218 r270 top
D6 "" SODFL2513X100/SOD323F/SC-90 37.109,41.942 r90 top
D7 "" SODFL2513X100/SOD323F/SC-90 37.109,22.317 r90 top
D8 "" SODFL2513X100/SOD323F/SC-90 37.109,4.343 r90 top
D9 "" SODFL2513X100/SOD323F/SC-90 28.905,56.794 r270 top
D10 "" SODFL2513X100/SOD323F/SC-90 28.905,38.737 r270 top
D11 "" SODFL2513X100/SOD323F/SC-90 28.905,20.76 r270 top
D12 "DIODE" SOD-323_L1.8-W1.3-LS2.5-RD 78.595,61.971 r90 top
D13 "D_LED_0603" LED0603-R-RD 114.3,32.385 r0 top
D14 "D_LED_0603" LED0603-R-RD 114.3,34.798 r0 top
D15 "PESD1CAN,215" SOT-23_L2.9-W1.3-P1.90-LS2.4-BR 118.44,52.299 r0 top
D16 "" SODFL2513X100/SOD323F/SC-90 78.546,23.292 r0 top
D17 "D_LED_0603" LED0603-R-RD 84.261,13.437 r90 top
D18 "TVS" SOD-323_L1.7-W1.3-LS2.5-BI 118.897,40.327 r90 top
G "TEST-Point" TP-1.0 32.156,18.186 r0 top (schematic designator TP24)
G "TEST-Point" TP-1.0 32.131,36.017 r90 top (schematic designator TP22)
G "TEST-Point" TP-1.0 31.928,54.432 r0 top (schematic designator TP20)
G "TEST-Point" TP-1.0 34.646,7.696 r90 top (schematic designator TP12)
G "TEST-Point" TP-1.0 34.646,25.908 r90 top (schematic designator TP10)
G "TEST-Point" TP-1.0 34.646,45.161 r90 top (schematic designator TP8)
HOU "TEST-Point" TP-1.0 68.428,29.083 r90 top (schematic designator TP11)
HOV "TEST-Point" TP-1.0 68.428,33.477 r180 top (schematic designator TP21)
HOW "TEST-Point" TP-1.0 68.428,37.846 r270 top (schematic designator TP36)
IBS+ "TEST-Point" TP-1.0 90.602,25.476 r90 top (schematic designator TP28)
IDC "TEST-Point" TP-1.0 115.164,26.238 r90 top (schematic designator TP47)
IU "TEST-Point" TP-1.0 97.974,3.277 r180 top (schematic designator TP34)
IV "TEST-Point" TP-1.0 87.182,3.277 r90 top (schematic designator TP37)
IW "TEST-Point" TP-1.0 99.898,21.488 r180 top (schematic designator TP33)
L1 "1uH 40A" IND-SMD_L12.6-W13.5 42.342,72.009 r90 top
L2 "ACT45B-510-2P-TL003" IND-SMD_4P-L4.5-W3.2-TL 110.49,42.824 r0 top
LIN "TEST-Point" TP-1.0 75.844,26.162 r90 top (schematic designator TP50)
LOU "TEST-Point" TP-1.0 70.545,32.639 r180 top (schematic designator TP19)
LOV "TEST-Point" TP-1.0 70.545,36.957 r180 top (schematic designator TP23)
LOW "TEST-Point" TP-1.0 70.79,41.072 r90 top (schematic designator TP45)
MARK7 "Comment" FM 10.033,4.597 r0 top locked
MARK8 "Comment" FM 126.467,4.293 r0 top
MARK9 "Comment" FM 126.467,85.7 r0 top
MCUFG "TEST-Point" TP-1.0 80.01,16.434 r180 top (schematic designator TP38)
MON "TEST-Point" TP-1.0 76.657,28.346 r0 top (schematic designator TP3)
NTCAD "TEST-Point" TP-1.0 115.189,20.269 r180 top (schematic designator TP51)
P1 "P_CON-1PIN" CON_63X08_P1 14.44,66.457 r270 top
P2 "Header 10X2" HDR2X10 126.086,34.925 r270 top
P3 "Header 6" HDR1X6 110.795,5.613 r0 top
P4 "" HDR1X2 122.098,59.944 r270 top
P5 "Header 7X2" HDR2X7 126.086,79.41 r270 top
P6 "P_CON-1PIN" CON_63X08_P1 14.44,79.309 r270 top
P7 "Header 6" HDR1X6 123.495,86.639 r180 top
P8 "" HDR1X2 126.086,45.425 r0 top
P9 "Header 3" HDR1X3 75.006,9.042 r0 top
P10 "" HDR1X2 104.47,86.639 r180 top
P11 "Header 3" HDR1X3 46.495,86.639 r180 top
P14 "P_CON-1PIN" CON_63X08_P1 14.44,48.518 r270 top
P15 "P_CON-1PIN" CON_63X08_P1 14.44,33.542 r270 top
P16 "P_CON-1PIN" CON_63X08_P1 14.44,13.517 r90 top
P23 "Header 2X2" HDR2X2 128.626,51.013 r90 top
P25 "Header 2" HDR1X2 128.626,40.327 r180 top
PGAIN "TEST-Point" TP-1.0 86.319,31.064 r90 top (schematic designator TP49)
PGAIP "TEST-Point" TP-1.0 91.653,31.064 r90 top (schematic designator TP46)
Q1 "SQJ138EP" PowerPAK_SO-8L_3_VIS#1 58.344,72.441 r180 top
Q2 "NPN" SOT95P240X110-3/SOT23/TO-236 68.123,83.16 r0 top
Q3 "SQJ138EP" PowerPAK_SO-8L_3_VIS#2 40.411,46.997 r270 top
Q4 "SQJ138EP" PowerPAK_SO-8L_3_VIS#1 40.411,27.748 r270 top
Q5 "SQJ138EP" PowerPAK_SO-8L_3_VIS#2 40.411,9.5 r270 top
Q6 "SQJ138EP" PowerPAK_SO-8L_3_VIS#3 26.333,51.308 r90 top
Q7 "SQJ138EP" PowerPAK_SO-8L_3_VIS#2 26.333,33.439 r90 top
Q8 "SQJ138EP" PowerPAK_SO-8L_3_VIS#2 26.333,15.57 r90 top
Q9 "BC847BPN,115" SOT-363_L2.0-W1.3-P0.65-LS2.1-TL 83.312,63.5 r180 top
Q10 "NPN" SOT95P240X110-3/SOT23/TO-236 75.253,13.769 r180 top
R1 "NC" R0603#1 95.682,33.782 r180 top
R2 "RES" R0603#1 109.601,32.334 r180 top
R3 "RES" R0603#1 109.601,34.722 r180 top
R4 "" R1206 78.511,18.593 r0 top
R5 "RES" R0603#1 67.031,78.156 r90 top
R6 "RES" R0603#1 118.529,29.845 r180 top
R7 "RES" R0603#1 67.945,75.641 r0 top
R8 "RES" R0603#1 105.308,30.074 r180 top
R9 "RES" R0603#1 108.28,78.994 r270 top
R10 "RES" R0603#1 105.308,28.213 r180 top
R11 "RES" R0603#1 113.055,83.591 r0 top
R12 "RES" R0603#1 116.434,83.591 r180 top
R13 "RES" R0603#1 111.658,74.32 r180 top
R14 "RES" R0603#1 111.658,71.628 r180 top
R15 "RES" R0603#1 118.529,71.628 r0 top
R16 "RES" R0603#1 111.658,69.24 r180 top
R17 "RES" R0603#1 118.516,69.266 r0 top
R18 "RES" R0603#1 111.658,66.667 r180 top
R19 "RES" R0603#1 118.529,66.667 r0 top
R20 "RES" R0603#1 118.529,64.186 r180 top
R21 "RES" R0603#1 109.601,37.77 r180 top
R22 "" R0603#1 34.696,41.028 r180 top
R23 "" R0603#1 34.696,21.504 r180 top
R24 "" R0603#1 34.696,3.658 r180 top
R25 "" R0603#1 34.696,42.628 r180 top
R26 "" R0603#1 34.696,23.13 r180 top
R27 "" R0603#1 34.696,5.258 r180 top
R28 "RES" R0603#1 105.308,26.352 r180 top
R29 "RES" R0603#1 105.308,24.492 r180 top
R30 "RES" R0603#1 105.308,22.631 r180 top
R31 "RES" R0603#1 70.088,30.861 r0 top
R32 "RES" R1206 40.538,42.755 r180 top
R33 "RES" R1206 40.538,23.003 r180 top
R34 "" R0603#1 31.344,57.658 r0 top
R35 "" R0603#1 31.344,39.496 r0 top
R36 "" R0603#1 31.344,21.674 r0 top
R37 "RES" R1206 40.538,5.207 r180 top
R38 "RES" R0603#1 70.088,35.179 r0 top
R39 "" R0603#1 77.368,54.407 r90 top
R40 "" R0603#1 31.344,56.032 r0 top
R41 "" R0603#1 31.344,37.845 r0 top
R42 "" R0603#1 31.344,19.972 r0 top
R43 "RES" R1206 75.625,62.56 r270 top
R44 "RES" R0603#1 70.088,39.497 r0 top
R45 "RES" R1206 25.578,55.956 r0 top
R46 "RES" R1206 25.578,37.946 r0 top
R47 "RES" R1206 25.578,19.998 r0 top
R48 "RES" R0603#1 104.419,49.073 r180 top
R49 "RES" R0603#1 101.422,56.312 r0 top
R50 "RES" R0603#1 118.135,59.284 r270 top
R51 "RES" R2512 38.633,54.508 r180 top
R52 "RES" R2512 38.633,35.814 r180 top
R53 "RES" R2512 38.633,15.672 r180 top
R54 "RES" R0603#1 89.875,28.372 r90 top
R55 "RES" R2512 46.939,35.814 r180 top
R56 "RES" R0603#1 115.443,58.471 r0 top
R57 "RES" R0603#1 115.443,60.096 r180 top
R58 "RES" R0603#1 88.224,28.372 r90 top
R59 "NC" R0402 110.49,43.961 r0 top
R60 "RES" R0603#1 111.354,53.162 r0 top
R61 "RES" R0603#1 108.052,46.457 r180 top
R62 "RES" R0603#1 94.717,44.526 r180 top
R63 "RES" R0603#1 111.354,51.384 r0 top
R64 "RES" R0603#1 69.215,22.047 r90 top
R65 "RES" R0603#1 94.717,40.64 r180 top
R66 "磁珠" R0603#2 78.867,26.137 r180 top
R67 "NC" R0402 110.49,41.688 r0 top
R68 "RES" R0603#1 101.389,5.994 r90 top
R69 "RES" R0603#1 103.389,18.821 r90 top
R70 "RES" R0603#1 105.057,18.821 r90 top
R71 "RES" R0603#1 103.057,5.994 r270 top
R72 "RES" R0603#1 99.935,18.821 r270 top
R73 "RES" R0603#1 97.935,5.994 r90 top
R74 "RES" R0603#1 106.725,18.821 r90 top
R75 "RES" R0603#1 104.725,5.994 r270 top
R76 "RES" R0603#1 106.705,14.097 r90 top
R77 "RES" R0603#1 106.705,10.338 r270 top
R78 "RES" R0603#1 70.764,22.047 r270 top
R79 "RES" R0603#1 108.077,48.387 r180 top
R80 "RES" R0603#1 90.84,5.994 r90 top
R81 "RES" R0603#1 101.422,60.579 r0 top
R82 "RES" R0603#1 92.491,18.821 r270 top
R83 "" R1206 78.511,21.133 r0 top
R84 "NC" R0603#1 72.314,13.894 r270 top
R85 "RES" R0603#1 90.84,18.821 r90 top
R86 "" R0603#1 118.504,25.654 r0 top
R87 "NC" R0603#1 118.504,24.028 r0 top
R88 "RES" R0603#1 83.21,66.116 r0 top
R89 "RES" R0603#1 92.491,5.994 r270 top
R90 "RES" R0603#1 87.208,5.994 r90 top
R91 "RES" R0603#1 81.305,13.805 r90 top
R92 "RES" R0603#1 94.133,5.994 r270 top
R93 "RES" R0603#1 80.781,63.528 r90 top
R94 "RES" R0603#1 79.731,13.805 r270 top
R95 "RES" R0603#1 94.904,10.338 r270 top
R96 "" R0603#1 87.208,18.821 r270 top
R97 "RES" R0603#1 85.765,66.941 r270 top
R98 "RES" R0603#1 83.21,67.716 r0 top
R99 "RES" R0603#1 85.765,63.528 r90 top
R100 "RES" R0603#1 80.781,66.941 r90 top
R101 "RES" R0603#1 118.529,34.798 r180 top
R102 "RES" R0603#1 118.529,32.41 r180 top
R103 "" R0603#1 118.504,21.488 r0 top
R104 "NC" R0603#1 118.504,19.812 r0 top
R105 "RES" R0603#1 84.287,17.132 r270 top
R106 "RES" R0603#1 84.287,20.46 r90 top
R107 "RES" R0603#1 87.198,21.311 r180 top
R108 "RES" R0603#1 112.192,14.961 r0 top
R109 "NTC" R0603#1 71.806,69.19 r90 top
R110 "RES" R0603#1 94.904,14.097 r270 top
R111 "NC" R0603#1 73.025,22.073 r270 top
R120 "NC" R0603#1 95.682,35.433 r180 top
R122 "RES" R0603#1 112.09,27.33 r0 top
R123 "RES" R0603#1 99.289,37.084 r180 top
RX "TEST-Point" TP-1.0 115.037,71.628 r90 top (schematic designator TP60)
S "TEST-Point" TP-1.0 32.08,50.622 r90 top (schematic designator TP27)
S "TEST-Point" TP-1.0 32.08,14.935 r90 top (schematic designator TP26)
S "TEST-Point" TP-1.0 32.08,32.779 r90 top (schematic designator TP25)
S "TEST-Point" TP-1.0 34.646,10.135 r90 top (schematic designator TP15)
S "TEST-Point" TP-1.0 34.646,28.397 r90 top (schematic designator TP14)
S "TEST-Point" TP-1.0 34.646,47.66 r90 top (schematic designator TP13)
SC1 "SCREW" pad#1 138.125,3.404 r0 top
SC2 "SCREW" pad#2 143.485,3.404 r0 top
SC3 "SCREW" pad#3 149.327,3.404 r0 top
SC4 "SCREW" pad#4 155.169,3.404 r0 top
SW1 "TS-1095PD-A6B2-D2" KEY-TH_4P-L6.0-W6.0-P3.90-LS6.5 114.935,78.994 r0 top
TP2 "TEST-Point" TP-1.0 66.929,80.569 r0 top
TX "TEST-Point" TP-1.0 115.037,69.147 r90 top (schematic designator TP59)
U1 "SPD1179" QFN48-0.5-1179-QFN50P700X700X90_HS-49M 83.402,38.616 r180 top
U2 "LDO钰泰" ESOP-8_L4.9-W3.9-P1.27-LS6.0-BL-EP 108.915,58.293 r90 top
U3 "TJA1044GT/3" SOIC-8_L4.9-W3.9-P1.27-LS6.0-BL 100.66,42.621 r270 top
U4 "AD8542ARZ-REEL7" SOIC-8_L4.9-W3.9-P1.27-LS6.0-BL 101.332,12.344 r0 top
U5 "AD8542ARZ-REEL7" SOIC-8_L4.9-W3.9-P1.27-LS6.0-BL 90.078,12.344 r0 top
VBAT "TEST-Point" TP-1.0 78.638,58.369 r180 top (schematic designator TP55)
VBAT_D "TEST-SMD" TEST-SMD_L2.7-W1.0 75.625,66.573 r0 top (schematic designator TP40)
VBATCP "TEST-Point" TP-1.0 75.625,58.471 r180 top (schematic designator TP56)
VBATdiv "TEST-Point" TP-1.0 115.265,24.13 r90 top (schematic designator TP61)
VBATM "TEST-Point" TP-1.0 77.902,51.918 r90 top (schematic designator TP57)
VCAP12 "TEST-Point" TP-1.0 86.106,56.896 r180 top (schematic designator TP54)
VCP "TEST-Point" TP-1.0 74.244,50.8 r180 top (schematic designator TP58)
VDD3 "TEST-Point" TP-1.0 84.363,23.266 r270 top (schematic designator TP53)
VDD5 "TEST-Point" TP-1.0 83.972,56.896 r180 top (schematic designator TP52)
VIO "TEST-Point" TP-1.0 106.248,39.497 r90 top (schematic designator TP32)
VPXU "TEST-Point" TP-1.0 76.26,32.182 r0 top (schematic designator TP7)
VPXV "TEST-Point" TP-1.0 76.26,36.03 r0 top (schematic designator TP9)
VPXW "TEST-Point" TP-1.0 76.26,39.878 r90 top (schematic designator TP44)
XRSTn "TEST-Point" TP-1.0 82.652,27.153 r0 top (schematic designator TP1)
Y1 "32MHz" CRYSTAL-SMD_4P-L3.2-W2.5-BL 99.441,33.731 r90 top

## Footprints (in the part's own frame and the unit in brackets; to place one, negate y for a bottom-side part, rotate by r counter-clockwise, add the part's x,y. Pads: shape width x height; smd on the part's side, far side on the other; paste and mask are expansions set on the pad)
C0603 [mm]
  rect 0.95x1 smd: 1(-0.8,0) 2(0.8,0)
  silkscreen extent -1.73,-0.75 1.73,0.75
C0805 [mm] "0805 Cap"
  rect 1.15x1.45 smd: 1(-0.9,0) 2(0.9,0)
  silkscreen extent -1.89,-0.95 1.89,0.95
C1206 [mm]
  rect 1.15x1.8 smd: 1(-1.5,0) 2(1.5,0)
  silkscreen extent -2.51,-1.1 2.51,1.1
CAP-SMD_BD10.0-L10.3-W10.3-FD [mm]
  rect 4.5x1.65 smd: 1(-4.5,0) 2(4.5,0)
  silkscreen extent -5.23,-5.23 5.23,5.23
CON_63X08_P1 [mm] "Insert terminal"
  oval 4x2.5 hole 1 slot 2.5 at 0 deg: 1(0,0) 1(5,0)
  silkscreen extent -3.75,-3.3 8.8,3.3
CRYSTAL-SMD_4P-L3.2-W2.5-BL [mm]
  rect 1.4x1.2 smd: 1(-1.1,-0.85) 2(1.1,-0.85) 3(1.1,0.85) 4(-1.1,0.85)
  silkscreen extent -2.26,-1.91 2.03,1.68
ESOP-8_L4.9-W3.9-P1.27-LS6.0-BL-EP [mm]
  rect 0.6x1.2 smd: 1(-1.905,-2.908) 2(-0.635,-2.908) 3(0.635,-2.908) 4(1.905,-2.908) 5(1.905,2.908) 6(0.635,2.908) 7(-0.635,2.908) 8(-1.905,2.908)
  rect 3.3x2.4 smd: 9(0,0)
  silkscreen extent -3.2,-2.67 2.55,2.05
FM [mm] "fiducial mark"
  round 1 smd paste-1 mask+0: 1(0,0)
  Top Layer keep-out circle w0.1: c0,0 r1.5
HDR1X2 [mm] "Connector; Header; 2 Position"
  rect 1.5x1.5 hole 0.9: 1(0,0)
  round 1.5 hole 0.9: 2(2.54,0)
  silkscreen extent -1.27,-1.27 3.81,1.27
HDR1X3 [mm] "Connector; Header; 3 Position"
  rect 1.5x1.5 hole 0.9: 1(0,0)
  round 1.5 hole 0.9: 2(2.54,0) 3(5.08,0)
  silkscreen extent -1.27,-1.27 6.35,1.27
HDR1X6 [mm] "Connector; Header; 6 Position"
  rect 1.5x1.5 hole 0.9: 1(0,0)
  round 1.5 hole 0.9: 2(2.54,0) 3(5.08,0) 4(7.62,0) 5(10.16,0) 6(12.7,0)
  silkscreen extent -1.27,-1.27 13.97,1.27
HDR2X2 [mm] "Connector; Header; 2x2 Position"
  rect 1.5x1.5 hole 0.9: 1(0,0)
  round 1.5 hole 0.9: 2(0,2.54) 3(2.54,0) 4(2.54,2.54)
  silkscreen extent -1.27,-1.27 3.81,3.81
HDR2X7 [mm] "Connector; Header; 7x2 Position"
  rect 1.5x1.5 hole 0.9: 1(0,0)
  round 1.5 hole 0.9: 2(0,2.54) 3(2.54,0) 4(2.54,2.54) 5(5.08,0) 6(5.08,2.54) 7(7.62,0) 8(7.62,2.54) 9(10.16,0) 10(10.16,2.54) 11(12.7,0) 12(12.7,2.54) 13(15.24,0) 14(15.24,2.54)
  silkscreen extent -1.27,-1.27 16.51,3.81
HDR2X10 [mm] "Connector; Header; 10x2 Position"
  rect 1.5x1.5 hole 0.9: 1(0,0)
  round 1.5 hole 0.9: 2(0,2.54) 3(2.54,0) 4(2.54,2.54) 5(5.08,0) 6(5.08,2.54) 7(7.62,0) 8(7.62,2.54) 9(10.16,0) 10(10.16,2.54) 11(12.7,0) 12(12.7,2.54) 13(15.24,0) 14(15.24,2.54) 15(17.78,0) 16(17.78,2.54) 17(20.32,0) 18(20.32,2.54) 19(22.86,0) 20(22.86,2.54)
  silkscreen extent -1.27,-1.27 24.13,3.81
IND-SMD_4P-L4.5-W3.2-TL [mm]
  rect 1.4x0.899 smd mask+0: 1(-2.281,1.25) 2(-2.281,-1.25) 3(2.281,-1.25) 4(2.281,1.25)
  silkscreen extent -2.2,-1.6 2.2,1.6
IND-SMD_L12.6-W13.5 [mm]
  rect 4.6x5 smd paste+0 mask+0: 1(-6,0) 2(6,0)
  silkscreen extent -7.1,-6.6 7.1,6.6
KEY-TH_4P-L6.0-W6.0-P3.90-LS6.5 [mm]
  round 2 hole 1.2: 1(-3.25,1.95) 2(3.25,1.95) 3(-3.25,-1.95) 4(3.25,-1.95)
  silkscreen extent -3,-3 3,3
LED0603-R-RD [mm]
  rect 0.8x0.8 smd: 1(0.851,0) 2(-0.851,0)
  silkscreen extent -2.08,-0.86 1.77,0.86
pad#1 [mm]
  round 3.5 hole 3.5: 3(-134.625,83.096)
pad#2 [mm]
  round 3.5 hole 3.5 mask+0: 3(-11.985,83.096)
pad#3 [mm]
  round 3.5 hole 3.5: 3(-145.827,0.096)
pad#4 [mm]
  round 3.5 hole 3.5: 3(-23.669,0.096)
PowerPAK_SO-8L_3_VIS#1 [mil]
  rect 21x60 smd paste+0 mask+0: 1(-75,-142) 2(-25,-142) 3(25,-142) 4(75,-142)
  rect 162x193 smd paste+0 mask+0: 5(0,44.5)
  Top Layer lines w10: 0,44.5 0,21.75 ; 0,29.75 54.25,-24.5 -67.25,-24.5 -13.01,29.75 50,29.75 54.25,34 -67.25,34 -38,63.25 50,63.25 66.75,80 -67.25,80
  silkscreen extent -104,-93 104,93
PowerPAK_SO-8L_3_VIS#2 [mil]
  rect 21x60 smd paste+0 mask+0: 1(-75,-142) 2(-25,-142) 3(25,-142) 4(75,-142)
  rect 162x193 smd paste+0 mask+0: 5(0,44.5)
  Top Layer lines w10: 0,21.75 0,44.5 ; 0,29.75 54.25,-24.5 -67.25,-24.5 -13.01,29.75 50,29.75 54.25,34 -67.25,34 -38,63.25 50,63.25 66.75,80 33.25,80 0,80 -0.25,80 -33.75,80 -67.25,80
  silkscreen extent -104,-93 104,93
PowerPAK_SO-8L_3_VIS#3 [mil]
  rect 21x60 smd paste+0 mask+0: 1(-75,-142) 2(-25,-142) 3(25,-142) 4(75,-142)
  rect 162x193 smd paste+0 mask+0: 5(0,44.5)
  Top Layer lines w10: -67.25,80 -33.75,80 -0.25,80 0,80 33.25,80 66.75,80 50,63.25 16.5,63.25 0,63.25 -17,63.25 -38,63.25 -50.5,50.75 -67.25,34 -33.75,34 -0.25,34 0,34 ; 0,44.5 0,34 ; 0,21.75 0,29.75 ; 0,34 0,29.75 ; 0,34 33.25,34 54.25,34 50,29.75 33.25,29.75 0,29.75 ; 0,29.75 4,25.75 43.75,-14 54.25,-24.5 33.25,-24.5 0,-24.5 -0.25,-24.5 -33.75,-24.5 -67.25,-24.5 -50.5,-7.75 -27.5,15.25 -13.01,29.75 -0.25,29.75 0,29.75 ; 0,29.75 0,29.75 ; 0,29.75 0,29.75 ; 0,29.75 0,29.75
  silkscreen extent -104,-93 104,93
QFN48-0.5-1179-QFN50P700X700X90_HS-49M [mm] "QFN, 48-Leads, Body 7.00x7.00mm, Pitch 0.50mm, Thermal Pad 5.20x5.20mm, IPC Low Density"
  oval 1.1x0.25 smd: 1(-3.675,2.75) 2(-3.675,2.25) 3(-3.675,1.75) 4(-3.675,1.25) 5(-3.675,0.75) 6(-3.675,0.25) 7(-3.675,-0.25) 8(-3.675,-0.75) 9(-3.675,-1.25) 10(-3.675,-1.75) 11(-3.675,-2.25) 12(-3.675,-2.75) 25(3.675,-2.75) 26(3.675,-2.25) 27(3.675,-1.75) 28(3.675,-1.25) 29(3.675,-0.75) 30(3.675,-0.25) 31(3.675,0.25) 32(3.675,0.75) 33(3.675,1.25) 34(3.675,1.75) 35(3.675,2.25) 36(3.675,2.75)
  oval 0.25x1.1 smd: 13(-2.75,-3.675) 14(-2.25,-3.675) 15(-1.75,-3.675) 16(-1.25,-3.675) 17(-0.75,-3.675) 18(-0.25,-3.675) 19(0.25,-3.675) 20(0.75,-3.675) 21(1.25,-3.675) 22(1.75,-3.675) 23(2.25,-3.675) 24(2.75,-3.675) 37(2.75,3.675) 38(2.25,3.675) 39(1.75,3.675) 40(1.25,3.675) 41(0.75,3.675) 42(0.25,3.675) 43(-0.25,3.675) 44(-0.75,3.675) 45(-1.25,3.675) 46(-1.75,3.675) 47(-2.25,3.675) 48(-2.75,3.675)
  rect 5.2x5.2 smd: 49(0,0)
  silkscreen extent -4.45,-3.68 3.68,3.67
R0402 [mm] "Resistor,Chip;1.00mm L X 0.50mm W"
  rect 0.59x0.64 smd: 1(-0.48,0) 2(0.48,0)
  silkscreen extent -0.95,-0.55 0.95,0.55
R0603#1 [mm] "Resistor,Chip;1.60mm L X 0.80mm W"
  rect 0.95x1 smd: 1(-0.8,0) 2(0.8,0)
  silkscreen extent 0,-0.5 0,0.5
R0603#2 [mm] "Resistor,Chip;1.60mm L X 0.80mm W"
  rect 0.95x1 smd: 1(-0.8,0) ""(0.8,0)
  silkscreen extent 0,-0.5 0,0.5
R1206 [mm] "Chip Resistor; Body 3.2 x 1.6 mm (LxW typ)"
  rect 1.15x1.8 smd: 1(-1.5,0) 2(1.5,0)
  silkscreen extent -2.3,-1.1 2.3,1.1
R2512 [mm]
  rect 1.283x3.456 smd: 1(-3.066,0) 2(3.066,0)
  silkscreen extent -3.94,-1.96 3.94,1.96
SMC/DO-214AB/Bidirect [mm]
  rect 3x3.8 smd: 1(3.301,0.102) 2(-3.649,0.112)
  silkscreen extent -3.27,-3.3 2.93,3.3
SOD-323_L1.7-W1.3-LS2.5-BI [mil]
  rect 31.5x31.5 smd mask+0: 1(-47.4,0) 2(47.4,0)
  silkscreen extent -34,-27 33,28
SOD-323_L1.8-W1.3-LS2.5-RD [mm]
  rect 1x0.75 smd: 1(-1.173,0) 2(1.173,0)
  silkscreen extent -0.85,-0.73 0.9,0.73
SODFL2513X100/SOD323F/SC-90 [mm]
  rect 0.84x0.46 smd: 1(-1.14,0) 2(1.14,0)
  silkscreen extent -2.03,-0.65 1.8,0.65
SOIC-8_L4.9-W3.9-P1.27-LS6.0-BL [mm]
  oval 0.588x2.045 smd: 1(-1.905,-2.773) 2(-0.635,-2.773) 3(0.635,-2.773) 4(1.905,-2.773) 5(1.905,2.773) 6(0.635,2.773) 7(-0.635,2.773) 8(-1.905,2.773)
  silkscreen extent -2.8,-2.92 2.53,1.52
SOT95P240X110-3/SOT23/TO-236 [mm]
  rect 1.05x0.8 smd: 1(-1.15,0.95) 2(-1.15,-0.95) 3(1.15,0)
  silkscreen extent -1.52,-1.45 0.3,1.92
SOT-23_L2.9-W1.3-P1.90-LS2.4-BR [mm]
  rect 1x0.8 smd mask+0: 1(1.15,-0.95) 2(1.15,0.95) 3(-1.15,0)
  silkscreen extent -0.7,-1.5 0.7,1.5
SOT-363_L2.0-W1.3-P0.65-LS2.1-TL [mm]
  rect 0.7x0.42 smd: 1(-0.92,0.65) 2(-0.92,0) 3(-0.92,-0.65) 4(0.92,-0.65) 5(0.92,0) 6(0.92,0.65)
  silkscreen extent -1.09,-1.1 0.7,1.24
TEST-SMD_L2.7-W1.0 [mm]
  rect 3.43x1.78 smd: 1(0,0)
TP-1.0 [mm]
  round 1 smd: 1(0,0)

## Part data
C1 C5 C6 C14 C15: library part CE_50V_220uF_10*10, "Capacitor polarized"
C2 C3 C10 C55: library part C_1206_10%_1, "MLCC"
C4 C7 C8 C9 C11 C12 C13 C16 C17 C18 C19 C20 C21 C22 C23 C24 C25 C26 C27 C28 C29 C30 C31 C32 C33 C34 C36 C37 C39 C40 C41 C42 C43 C44 C45 C46 C47 C48 C50 C51 C52 C53 C54 C56 C57 C58 C59 C60 C61 C62 C63 C64 C65 C66 C67 C68 C69 C70 C71 C72 C73 C74 C75 C76 C77 C78 C79 C80 C81 C82 C83 C84 C90: library part C_0603_10%_1, "MLCC"
C35 C38 C49: library part C_0805_10%_1, "MLCC"
D1: library part D_TVS_SMC, "TVS Bidirectional"
D2 D3 D4 D5 D6 D7 D8 D9 D10 D11 D16: library part D_1N4148WS, "Diode SOD323"
D12: library part D_SMA, "Diode"
D15: library part D_PESD1CAN,215
D18: library part D_ESD_BI_SOD323, "ESD TVS Bidirectional"
L1: library part L_SER2000
L2: library part L_ACT45B-510-2P-TL003
P1 P6 P14 P15 P16: "Insert terminal,快接端子 6.3mm*0.8厚 插片"
P2: "Header, 10-Pin, Dual row"
P3 P7: "Header, 6-Pin"
P4 P8 P10: library part "Header 2", "Header, 2-Pin"
P5: "Header, 7-Pin, Dual row"
P9 P11: "Header, 3-Pin"
P23: "Header, 2-Pin, Dual row"
P25: "Header, 2-Pin"
Q1 Q3 Q4 Q5 Q6 Q7 Q8: library part Q_N_DFN-8L_5*6, "N-CHANNEL"
Q2 Q10: library part Q_8050
Q9: library part Q_BC847BPN,115
R1 R2 R3 R5 R6 R7 R8 R9 R10 R11 R12 R13 R14 R15 R16 R17 R18 R19 R20 R21 R22 R23 R24 R25 R26 R27 R28 R29 R30 R31 R34 R35 R36 R38 R39 R40 R41 R42 R44 R48 R49 R50 R54 R56 R57 R58 R60 R61 R62 R63 R64 R65 R66 R68 R69 R70 R71 R72 R73 R74 R75 R76 R77 R78 R79 R80 R81 R82 R84 R85 R86 R87 R88 R89 R90 R91 R92 R93 R94 R95 R96 R97 R98 R99 R100 R101 R102 R103 R104 R105 R106 R107 R108 R110 R111 R120 R122 R123: library part R_0603_1/10W_1%_1, "Thick film"
R4 R32 R33 R37 R43 R45 R46 R47 R83: library part R_1206_1/4W_1%_1, "Thick film"
R51 R52 R53 R55: library part R_2512_1, "Thick film"
R59 R67: library part R_0402_1/16W_1%_1, "Thick film"
R109: library part R_NTC_5R_2A_P5mm, "10kΩ 电阻精度:±0.5% 3380K  NTCG163JX103DT1S"
SW1: library part SW_TH_4P_L6.0W6.0_P3.9_LS6.5, "TH 3.9*6.5"
U1: library part U_SPD1179, "32-bit ARM CM4 automotives MCU with HV power management, LIN and PDRV"
U2: library part U_LDO_EQ5430
U3: library part U_TJA1044GT/3, "CAN transceiver CAN FD"
U4 U5: library part U_LM2904DT
VBAT_D: "测试点/测试环,5017"
Y1: library part Z_32MHz_SMD

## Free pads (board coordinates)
  round 10 hole 4.5: 1(5.918,16.042) 1(5.918,31.017) 1(5.918,45.993) 1(5.918,63.932) 1(5.918,76.784)

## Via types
v1: diameter 0.7, hole 0.3, Top Layer to Bottom Layer, tented both sides, 693 vias
v2: diameter 0.5, hole 0.2, Top Layer to Bottom Layer, tented both sides, 154 vias
v3: diameter 0.9, hole 0.5, Top Layer to Bottom Layer, 60 vias
v4: diameter 0.5, hole 0.2, Top Layer to Bottom Layer, 32 vias

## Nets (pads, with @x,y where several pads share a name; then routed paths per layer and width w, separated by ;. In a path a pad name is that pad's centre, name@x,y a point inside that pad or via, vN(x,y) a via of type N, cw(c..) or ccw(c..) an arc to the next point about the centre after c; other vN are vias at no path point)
1.65V: 1.65.1 C65.1 C66.1 C74.2 C82.1 R76.1 R77.1 R95.1 R110.1 | length 29.9
  Top Layer w0.254: R95.1@94.904,11.138 C82.1@96.987,11.138 C74.2@96.987,13.297 ; R110.1@94.904,14.897 R110.1@94.929,14.897 ; 1.65.1@95.996,21.488 95.996,15.989 95.277,15.27 95.277,15.245 R110.1@94.929,14.897 ; C66.1@108.687,11.138 R77.1@106.705,11.138 R76.1@106.705,13.297 ; C65.1@108.687,13.297 R76.1@106.705,13.297 ; R110.1@94.929,14.897 96.181,13.645 96.639,13.645 C74.2@96.987,13.297 ; C74.2@96.987,13.297 R76.1@106.705,13.297
5V_COM: C44.2 C58.2 P4.1 P4.2 R50.2 U2.1 U3.3 | length 48.3
  Top Layer w0.254: C44.2@115.532,56.49 116.567,57.525 117.151,57.525 118.11,58.484 R50.2@118.135,58.484
  Top Layer w0.508: C58.2@95.517,42.596 95.517,42.571 96.101,41.986 U3.3@97.888,41.986 98.616,41.986 99.746,43.116 99.746,50.648 103.911,54.813 113.856,54.813 C44.2@115.286,56.244 ; U2.1@111.823,56.388 112.123,56.388 112.225,56.49 C44.2@115.532,56.49 115.532,56.465 117.006,54.991 119.685,54.991 P4.2@122.098,57.404 P4.1@122.098,59.944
